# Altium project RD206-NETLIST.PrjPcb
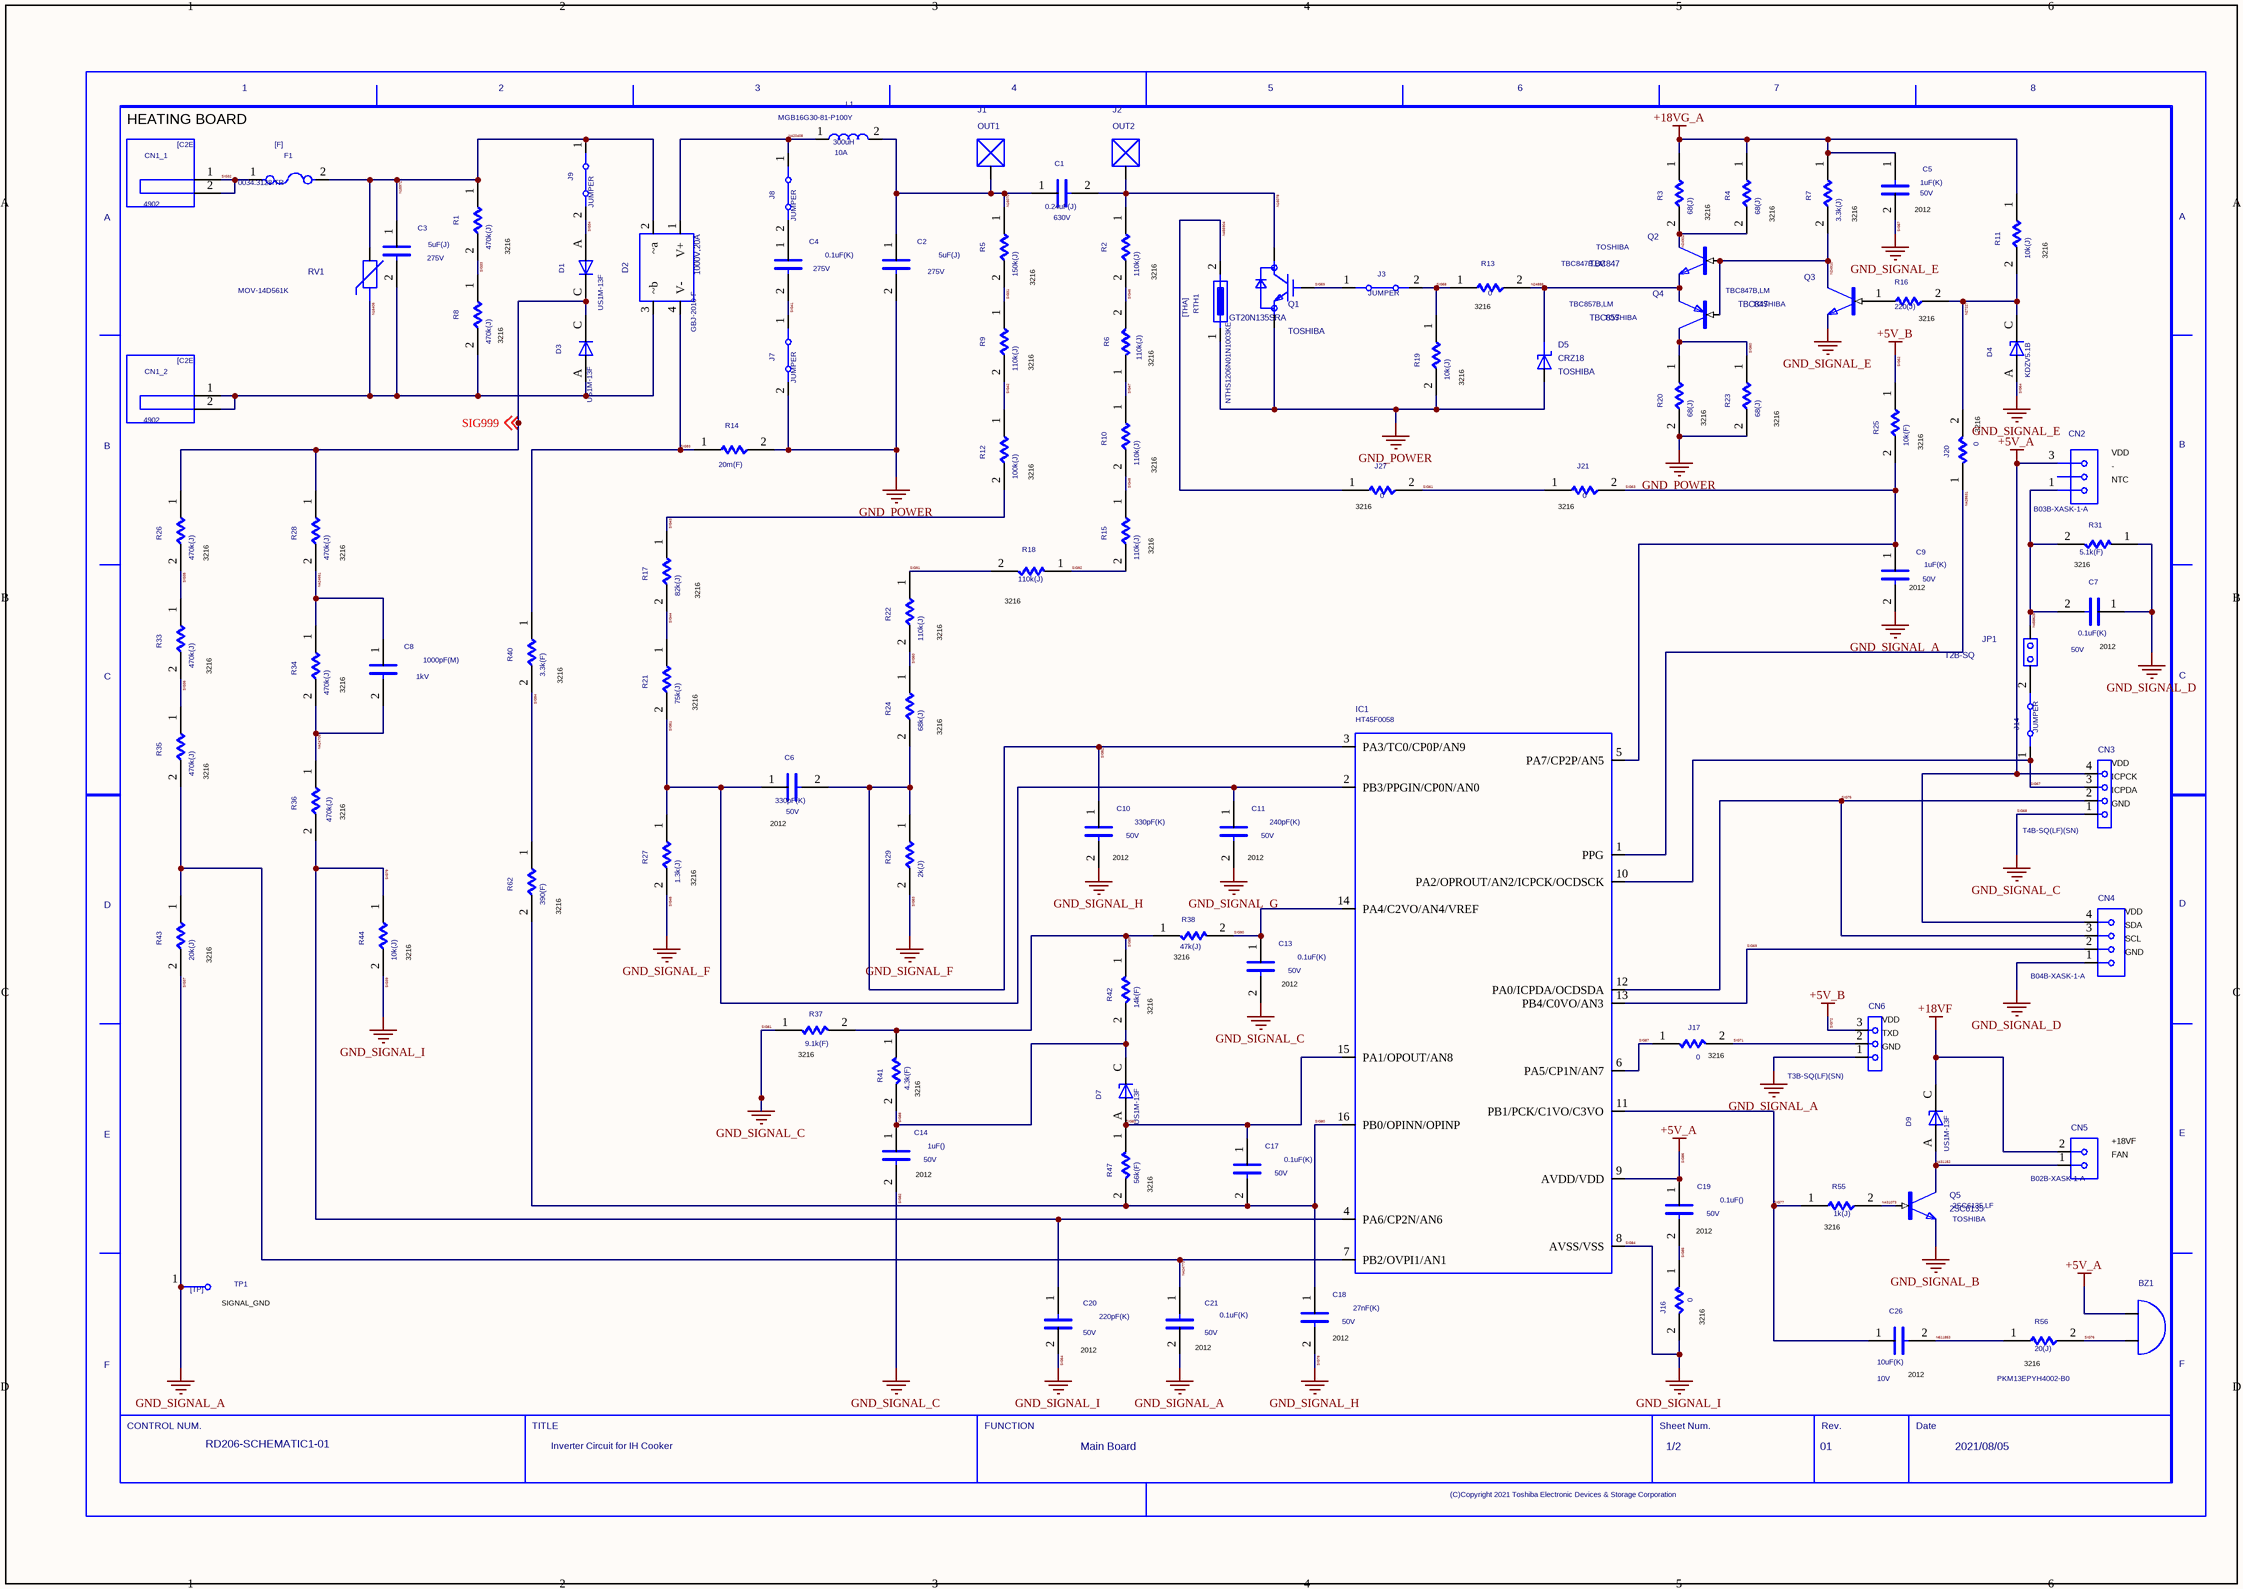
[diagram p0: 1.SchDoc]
2 sheets, 144 parts. Net scope: global (net labels, ports and power ports of the same name join across sheets).
Sheets:
  1.SchDoc
  2.SchDoc

## Sheet 1.SchDoc
size 420 x 297 mm

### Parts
(Parts that share a designator on the sheet are numbered #1, #2 ... from top to bottom, then left to right.)
BZ1  PKM13EPYH4002-B0  [DIP]
C1  VAL2: 630V  VAL1: 0.24uF(J)  (hidden comment: C)
C2  VAL2: 275V  VAL1: 5uF(J)  (hidden comment: C)
C3  VAL2: 275V  VAL1: 5uF(J)  (hidden comment: C)
C4  VAL2: 275V  VAL1: 0.1uF(K)  (hidden comment: C)
C5  VAL2: 50V  VAL1: 1uF(K)  (hidden comment: C)
C6  VAL2: 50V  VAL1: 330pF(K)  (hidden comment: C)
C7  VAL2: 50V  VAL1: 0.1uF(K)  (hidden comment: C)
C8  VAL2: 1kV  VAL1: 1000pF(M)  (hidden comment: C)
C9  VAL2: 50V  VAL1: 1uF(K)  (hidden comment: C)
C10  VAL2: 50V  VAL1: 330pF(K)  (hidden comment: C)
C11  VAL2: 50V  VAL1: 240pF(K)  (hidden comment: C)
C13  VAL2: 50V  VAL1: 0.1uF(K)  (hidden comment: C)
C14  VAL2: 50V  VAL1: 1uF()  (hidden comment: C)
C17  VAL2: 50V  VAL1: 0.1uF(K)  (hidden comment: C)
C18  VAL2: 50V  VAL1: 27nF(K)  (hidden comment: C)
C19  VAL2: 50V  VAL1: 0.1uF()  (hidden comment: C)
C20  VAL2: 50V  VAL1: 220pF(K)  (hidden comment: C)
C21  VAL2: 50V  VAL1: 0.1uF(K)  (hidden comment: C)
C26  VAL2: 10V  VAL1: 10uF(K)  (hidden comment: C)
CN1_1  VAL3: 4902  (hidden comment: C2E)
CN1_2  VAL3: 4902  (hidden comment: C2E)
CN2  VAL3: B03B-XASK-1-A  (hidden comment: CON3S)
CN3  VAL3: T4B-SQ(LF)(SN)  [DIP]  (hidden comment: T4B-SQ)
CN4  B04B-XASK-1-A  [DIP]
CN5  B02B-XASK-1-A  [DIP]
CN6  VAL3: T3B-SQ(LF)(SN)  [DIP]  (hidden comment: T3B-SQ)
D1  VAL3: US1M-13F  (hidden comment: D)
D2  VALUE2: 1000V,20A  VAL3: GBJ-2010-F  [SMA]  (hidden comment: GBJ2010)
D3  VAL3: US1M-13F  (hidden comment: D)
D4  VAL3: KDZV5.1B  (hidden comment: ZD)
D5  CRZ18  MANUFACTURER: TOSHIBA  [S-FLAT]
D7  VAL3: US1M-13F  (hidden comment: ZD)
D9  VAL3: US1M-13F  (hidden comment: ZD)
F1  VAL3: 0034.3128.TR  (hidden comment: F)
IC1  HT45F0058
J1  OUT1
J2  OUT2
J3  VAL3: JUMPER  (hidden comment: JP)
J7  VAL3: JUMPER  (hidden comment: JP)
J8  VAL3: JUMPER  (hidden comment: JP)
J9  VAL3: JUMPER  (hidden comment: JP)
J14  VAL3: JUMPER  (hidden comment: JP)
J16  VAL1: 0  (hidden comment: R)
J17  VAL1: 0  (hidden comment: R)
J20  VAL1: 0  (hidden comment: R)
J21  VAL1: 0  (hidden comment: R)
J27  VAL1: 0  (hidden comment: R)
JP1  T2B-SQ  [DIP]
L1  VAL3: MGB16G30-81-P100Y  VAL2: 10A  VAL1: 300uH  (hidden comment: L)
Q1  GT20N135SRA  MANUFACTURER: TOSHIBA  [TO-247]
Q2  TBC847  USERCOMPTEXT3: TOSHIBA  VAL3: TBC847B,LM  [SOT-23]
Q3  TBC847  USERCOMPTEXT3: TOSHIBA  VAL3: TBC847B,LM  [SOT-23]
Q4  TBC857  USERCOMPTEXT3: TOSHIBA  VAL3: TBC857B,LM  [SOT-23]
Q5  2SC6135  USERCOMPTEXT3: TOSHIBA  VAL3: 2SC6135,LF  [SOT-323]
R1  VAL1: 470k(J)  (hidden comment: R)
R2  VAL1: 110k(J)  (hidden comment: R)
R3  VAL1: 68(J)  (hidden comment: R)
R4  VAL1: 68(J)  (hidden comment: R)
R5  VAL1: 150k(J)  (hidden comment: R)
R6  VAL1: 110k(J)  (hidden comment: R)
R7  VAL1: 3.3k(J)  (hidden comment: R)
R8  VAL1: 470k(J)  (hidden comment: R)
R9  VAL1: 110k(J)  (hidden comment: R)
R10  VAL1: 110k(J)  (hidden comment: R)
R11  VAL1: 10k(J)  (hidden comment: R)
R12  VAL1: 100k(J)  (hidden comment: R)
R13  VAL1: 0  (hidden comment: R)
R14  VAL1: 20m(F)  (hidden comment: R)
R15  VAL1: 110k(J)  (hidden comment: R)
R16  VAL1: 220(J)  (hidden comment: R)
R17  VAL1: 82k(J)  (hidden comment: R)
R18  VAL1: 110k(J)  (hidden comment: R)
R19  VAL1: 10k(J)  (hidden comment: R)
R20  VAL1: 68(J)  (hidden comment: R)
R21  VAL1: 75k(J)  (hidden comment: R)
R22  VAL1: 110k(J)  (hidden comment: R)
R23  VAL1: 68(J)  (hidden comment: R)
R24  VAL1: 68k(J)  (hidden comment: R)
R25  VAL1: 10k(F)  (hidden comment: R)
R26  VAL1: 470k(J)  (hidden comment: R)
R27  VAL1: 1.3k(J)  (hidden comment: R)
R28  VAL1: 470k(J)  (hidden comment: R)
R29  VAL1: 2k(J)  (hidden comment: R)
R31  VAL1: 5.1k(F)  (hidden comment: R)
R33  VAL1: 470k(J)  (hidden comment: R)
R34  VAL1: 470k(J)  (hidden comment: R)
R35  VAL1: 470k(J)  (hidden comment: R)
R36  VAL1: 470k(J)  (hidden comment: R)
R37  VAL1: 9.1k(F)  (hidden comment: R)
R38  VAL1: 47k(J)  (hidden comment: R)
R40  VAL1: 3.3k(F)  (hidden comment: R)
R41  VAL1: 4.3k(F)  (hidden comment: R)
R42  VAL1: 14k(F)  (hidden comment: R)
R43  VAL1: 20k(J)  (hidden comment: R)
R44  VAL1: 10k(J)  (hidden comment: R)
R47  VAL1: 56k(F)  (hidden comment: R)
R55  VAL1: 1k(J)  (hidden comment: R)
R56  VAL1: 20(J)  (hidden comment: R)
R62  VAL1: 390(F)  (hidden comment: R)
RTH1  VAL3: NTHS1206N01N1003KE  (hidden comment: THA)
RV1  VAL3: MOV-14D561K  (hidden comment: VARISTOR)
TP1  TP  (value not drawn)
U?#1  DATE: 2021/08/05  DRAWINGNUMBER: RD206-SCHEMATIC1-01  FUNCTION: Main Board  REVISION: 01  SHEETNUMBER: 1/2  TITLE: Inverter Circuit for IH Cooker  (hidden comment: WAKU_DEF100)

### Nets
+18VF: CN5.2 D9.C
+18VG_A: C5.1 R3.1 R4.1 R7.1 R11.1  [project net SIG26]
GND_POWER: C2.2 D5.A(Anode) J7.2 Q1.3(EMITTER) R14.2 R19.2 R20.2 R23.2 RTH1.1
GND_SIGNAL_A: C9.2 C21.2 CN6.1 R43.2 TP1.1  [also labelled SIG37]  [project net SIG29]
GND_SIGNAL_B: Q5.2(E)  [project net SIG15]
GND_SIGNAL_D: C7.1 CN4.1 R31.1
GND_SIGNAL_G: C11.2
GND_SIGNAL_I: C20.2 IC1.8(AVSS/VSS) J16.2 R44.2  [also labelled SIG39, SIG54, SIG84]  [project net SIG28]
SIG45: R27.2 R29.2  [also labelled GND_SIGNAL_F, SIG53]
SIG57: C5.2 D4.A Q3.2(E)  [also labelled GND_SIGNAL_E, SIG64]
SIG62: CN6.3 R25.1  [also labelled +5V_B, SIG72]
SIG68: C13.2 C14.2 CN3.1 R37.1  [also labelled GND_SIGNAL_C, SIG81, SIG82]
SIG78: C10.2 C18.2  [also labelled GND_SIGNAL_H]
SIG86: BZ1.1 C19.1 CN2.3 CN3.4 CN4.4 IC1.9(AVDD/VDD)  [also labelled +5V_A]
N15972: C3.1 D2.2(~a) F1.2 J9.1 R1.1 RV1.1
N16070: C1.1 C2.1 J1.1 L1.2 R5.1
N16078: C1.2 J2.1 Q1.2(COLLECTOR) R2.1
N16406: C3.2 CN1_2.1 CN1_2.2 D2.3(~b) D3.A R8.2 RV1.2
N24888: D5.C(Cathode) Q2.2(E) Q4.2(E) R13.2
N24902: Q2.3(C) R3.2 R4.2
N24910: Q2.1(B) Q3.3(C) Q4.1(B) R7.2
N27227: D4.C J20.2 R11.2 R16.2
N420408: D2.1(V+) J8.1 L1.1
N424661: C8.1 R28.2 R34.1
N424705: C8.2 R34.2 R36.1
N424773: C21.1 IC1.7(PB2/OVPI1/AN1) R35.2 R43.1
N428631: IC1.1(PPG) J20.1
N431073: Q5.1(B) R55.2
N431152: CN5.1 D9.A Q5.3(C)
N456904: J27.1 RTH1.2
N458626: C7.2 CN2.1 JP1.2 R31.2
N611853: C26.2 R56.1
SIG31: R5.2 R9.1
SIG32: CN1_1.1 CN1_1.2 F1.1
SIG33: R1.2 R8.1
SIG34: D1.A J9.2
SIG35: R26.2 R33.1
SIG36: R33.2 R35.1
SIG41: C4.2 J7.1
SIG42: R9.2 R12.1
SIG43: R12.2 R17.1
SIG44: R17.2 R21.1
SIG46: R2.2 R6.2
SIG47: R6.1 R10.1
SIG48: R10.2 R15.1
SIG50: R22.2 R24.1
SIG51: C6.1 C11.1 IC1.2(PB3/PPGIN/CP0N/AN0) R21.2 R27.1
SIG52: C6.2 C10.1 IC1.3(PA3/TC0/CP0P/AN9) R24.2 R29.1
SIG58: J3.2 R13.1 R19.1
SIG59: J3.1 Q1.1(GATE)
SIG60: Q4.3(C) R20.1 R23.1
SIG61: J21.1 J27.2
SIG63: C9.1 IC1.5(PA7/CP2P/AN5) J21.2 R25.2
SIG67: CN3.3 IC1.10(PA2/OPROUT/AN2/ICPCK/OCDSCK) J14.1
SIG69: CN4.2 IC1.13(PB4/C0VO/AN3)
SIG71: CN6.2 J17.2
SIG75: CN3.2 CN4.3 IC1.12(PA0/ICPDA/OCDSDA)
SIG76: BZ1.2 R56.2
SIG77: C26.1 IC1.11(PB1/PCK/C1VO/C3VO) R55.1
SIG79: C20.1 IC1.4(PA6/CP2N/AN6) R36.2 R44.1
SIG80: C17.2 C18.1 IC1.16(PB0/OPINN/OPINP) R47.2 R62.2
SIG83: C17.1 D7.A IC1.15(PA1/OPOUT/AN8) R47.1
SIG85: C19.2 J16.1
SIG87: IC1.6(PA5/CP1N/AN7) J17.1
SIG88: C14.1 D7.C R41.2 R42.2
SIG89: R37.2 R38.1 R41.1 R42.1
SIG90: C13.1 IC1.14(PA4/C2VO/AN4/VREF) R38.2
SIG91: R18.2 R22.1
SIG92: R15.2 R18.1
SIG93: D2.4(V-) R14.1 R40.1
SIG94: R40.2 R62.1
SIG999: D1.C D3.C R26.1 R28.1 ; off-sheet SIG999
NetC4_1: C4.1 J8.2
NetJ14_2: J14.2 JP1.1
NetQ3_1: Q3.1(B) R16.1

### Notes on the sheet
- HEATING BOARD
- (near R1) 3216
- 3216
- (near R4) 3216
- (near C5) 2012
- (near R11) 3216
- (near R5) 3216
- (near R2) 3216
- (near R13) 3216
- (near R16) 3216
- (near R8) 3216
- (near R9) 3216
- (near R6) 3216
- (near R19) 3216
- (near R20) 3216
- (near R23) 3216
- (near J20) 3216
- VDD
- (near R12) 3216
- (near R10) 3216
- (near J27) 3216
- (near J21) 3216
- -
- NTC
- (near R26) 3216
- (near R28) 3216
- (near R17) 3216
- (near R15) 3216
- (near C9) 2012
- (near R31) 3216
- (near R22) 3216
- (near R18) 3216
- (near C7) 2012
- (near R33) 3216
- (near R40) 3216
- (near R21) 3216
- (near R24) 3216
- (near R35) 3216
- (near CN3) VDD
- (near CN3) ICPCK
- (near CN3) ICPDA
- (near R36) 3216
- (near C6) 2012
- (near C10) 2012
- (near C11) 2012
- (near CN3) GND
- (near R62) 3216
- (near R27) 3216
- (near CN4) VDD
- (near CN4) SDA
- (near R43) 3216
- (near R44) 3216
- (near R38) 3216
- (near C13) 2012
- (near CN4) GND
- (near CN4) SCL
- (near R37) 3216
- (near R42) 3216
- (near J17) 3216
- (near CN6) TXD
- (near CN6) GND
- (near CN6) VDD
- (near R41) 3216
- (near C14) 2012
- (near R47) 3216
- (near CN5) FAN
- (near CN5) +18VF
- (near C19) 2012
- (near R55) 3216
- (near TP1) SIGNAL_GND
- (near C18) 2012
- (near J16) 3216
- (near C20) 2012
- (near C21) 2012
- (near C26) 2012
- (near R56) 3216

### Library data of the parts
BZ1 = BUZZER: PARTNAME: Part13801; MANUFACTURER: Murata; TIME: 16:07:41; UPDATEUSER: t5459927; SAVECOUNT: 1; OriginalSymbolOrigin: (0,0); VALUE2: D12.6xH6.9,4kHz; INSTANCENAME: INS611789
C1 = C: PARTNAME: Part13608; OriginalSymbolOrigin: (2540,7620)
C2 C3 = C: PARTNAME: Part13609; OriginalSymbolOrigin: (2540,7620)
C4 = C: PARTNAME: Part13606; OriginalSymbolOrigin: (2540,7620)
C5 C20 C21 = C#1: PARTNAME: Part6003; OriginalSymbolOrigin: (2540,7620); CaptureCellPackProp: C##1
C6 C7 C9-C11 C13 C14 C17-C19 C26 = C: PARTNAME: Part6003; OriginalSymbolOrigin: (2540,7620)
C8 = C: PARTNAME: Part13607; OriginalSymbolOrigin: (2540,7620)
CN1_1 CN1_2 = C2E: PARTNAME: Part13901; SAVEAREA0: -4733,-209,25099,17942; TIME: 14:34:38; UPDATEUSER: fukuda-y; UPDATETIME: 16:35:06; SAVECOUNT: 10; OriginalSymbolOrigin: (5080,15240)
CN2 = CON3S: PARTNAME: Part13910; TIME: 16:07:41; UPDATEUSER: t5459927; UPDATETIME: 14:26:02; SAVECOUNT: 3; SAVEAREA0: -3803,-10405,11105,524; OriginalSymbolOrigin: (0,0)
CN3 = HEADER_4P: PARTNAME: Part13906; MANUFACTURER: JST; TIME: 16:07:41; UPDATEUSER: t5459927; SAVECOUNT: 1; SAVEAREA0: -6996,-12954,11642,710; OriginalSymbolOrigin: (0,0); VALUE2: for Debugger,(NM); INSTANCENAME: INS493247
CN4 = CON4S: PARTNAME: Part13904; MANUFACTURER: JST; TIME: 16:07:41; UPDATEUSER: t5459927; SAVECOUNT: 1; SAVEAREA0: -5711,-12954,12927,710; OriginalSymbolOrigin: (0,0); VALUE2: to DISPLAY BOARD; INSTANCENAME: INS493000
CN5 = CON2S: PARTNAME: Part13902; MANUFACTURER: JST; TIME: 16:07:41; UPDATEUSER: t5459927; SAVECOUNT: 1; SAVEAREA0: -1901,-7788,9280,409; OriginalSymbolOrigin: (0,0); VALUE2: to FAN; INSTANCENAME: INS493353
CN6 = HEADER_3P: PARTNAME: Part13908; MANUFACTURER: JST; TIME: 16:07:41; UPDATEUSER: t5459927; SAVECOUNT: 1; SAVEAREA0: -5093,-10384,9816,546; OriginalSymbolOrigin: (0,0); VALUE2: for UART Debug; INSTANCENAME: INS667453
D1 D3 = D: PARTNAME: Part13451; SAVEAREA0: -225,-91,12804,7836; SAVECOUNT: 3; TIME: 14:49:55; UPDATEUSER: 19870035; UPDATETIME: 14:20:16; OriginalSymbolOrigin: (5080,5080)
D2 = D25XB: PARTNAME: Part13452; MANUFACTURER: DIODES; TIME: 16:07:41; UPDATEUSER: t5459927; SAVECOUNT: 1; SAVEAREA0: -3247,-11751,15521,2008; OriginalSymbolOrigin: (0,0); INSTANCENAME: INS420197
D4 = ZD: PARTNAME: Part4291; SAVEAREA0: -4630,-153,17114,13055; TIME: 14:49:55; UPDATEUSER: fukuda-y; UPDATETIME: 08:18:42; SAVECOUNT: 6; OriginalSymbolOrigin: (5080,5080)
D5 = DIODE_ZENER: PARTNAME: Part4291; TIME: 16:07:41; UPDATEUSER: t5459927; SAVECOUNT: 1; OriginalSymbolOrigin: (0,0); INSTANCENAME: INS25179
D7 D9 = ZD: PARTNAME: Part13451; SAVEAREA0: -4630,-153,17114,13055; TIME: 14:49:55; UPDATEUSER: fukuda-y; UPDATETIME: 08:18:42; SAVECOUNT: 6; OriginalSymbolOrigin: (5080,5080)
F1 = F: PARTNAME: Part13701; OriginalSymbolOrigin: (2540,5080); VAL2: 12.5A 250VAC
IC1 = HT45F0058: PARTNAME: Part2183; MANUFACTURER: HOLTEK; TIME: 16:07:41; UPDATEUSER: t5459927; UPDATETIME: 09:12:11; SAVECOUNT: 2; SAVEAREA0: -96097,-76323,141060,32998; OriginalSymbolOrigin: (0,0)
J1 = TERMINAL: PARTNAME: Part13909; PART_NUMBER: for Heating coil; TIME: 16:07:41; UPDATEUSER: t5459927; SAVECOUNT: 1; SAVEAREA0: -3180,-7788,8001,409; OriginalSymbolOrigin: (0,0); INSTANCENAME: INS418589
J2 = TERMINAL: PARTNAME: Part13909; PART_NUMBER: for Heating coil; TIME: 16:07:41; UPDATEUSER: t5459927; SAVECOUNT: 1; SAVEAREA0: -3180,-7788,8001,409; OriginalSymbolOrigin: (0,0); VAL3: OUT1; INSTANCENAME: INS418681
J3 J7 J8 = JP: PARTNAME: Part13917; OriginalSymbolOrigin: (2540,5080)
J9 J14 = JP: PARTNAME: Part13915; OriginalSymbolOrigin: (2540,5080)
J16 J17 J20 J21 J27 R1-R13 R15-R29 R31 R33-R37 R40-R44 R47 R55 R56 R62 = R: PARTNAME: Part4004; OriginalSymbolOrigin: (5080,5080)
JP1 = HEADER: PARTNAME: Part13905; MANUFACTURER: JST; TIME: 16:07:41; UPDATEUSER: t5459927; SAVECOUNT: 1; SAVEAREA0: -2956,-6337,7768,1525; OriginalSymbolOrigin: (0,0); VAL3: T2B-SQ(LF)(SN); INSTANCENAME: INS520211
L1 = L: PARTNAME: Part13301; OriginalSymbolOrigin: (2540,5080)
Q1 = IGBT: PARTNAME: Part13501; TIME: 16:07:41; UPDATEUSER: t5459927; SAVECOUNT: 1; OriginalSymbolOrigin: (0,0); INSTANCENAME: INS24255
Q2 = 2SC: PARTNAME: Part5004; TIME: 16:07:41; UPDATEUSER: t5459927; SAVECOUNT: 1; OriginalSymbolOrigin: (0,2540); INSTANCENAME: INS24481
Q3 = 2SC: PARTNAME: Part5004; TIME: 16:07:41; UPDATEUSER: t5459927; SAVECOUNT: 1; OriginalSymbolOrigin: (0,2540); INSTANCENAME: INS24374
Q4 = 2SA: PARTNAME: Part5004; TIME: 16:07:41; UPDATEUSER: t5459927; SAVECOUNT: 1; OriginalSymbolOrigin: (0,2540); INSTANCENAME: INS24550
Q5 = 2SC: PARTNAME: Part13502; TIME: 16:07:41; UPDATEUSER: t5459927; SAVECOUNT: 1; OriginalSymbolOrigin: (0,2540); INSTANCENAME: INS429563
R14 = R: PARTNAME: Part13402; OriginalSymbolOrigin: (5080,5080)
R38 = R#1: PARTNAME: Part4004; OriginalSymbolOrigin: (5080,5080); CaptureCellPackProp: R##1
RTH1 = THA: PARTNAME: Part3109; SAVECOUNT: 3; SAVEAREA0: -562,-143,15615,10489; TIME: 16:37:29; UPDATEUSER: sato-yr; OriginalSymbolOrigin: (2540,5080)
RV1 = VARISTOR: PARTNAME: Part13302; TIME: 16:07:41; UPDATEUSER: t5459927; UPDATETIME: 09:40:33; SAVECOUNT: 2; SAVEAREA0: -22723,-23461,27592,13427; OriginalSymbolOrigin: (0,-2540)
TP1 = TP: PARTNAME: Part13998; TIME: 16:12:21; UPDATEUSER: fukuda-y; UPDATETIME: 16:18:11; SAVECOUNT: 2; SAVEAREA0: -242,-92,12810,7836; OriginalSymbolOrigin: (0,7620)
U?#1 = WAKU_DEF100: PLOTTIME: HH:MM; SAVEAREA0: 148187,-66180,486823,89919; TIME: 14:30:25; UPDATEUSER: t5459927; UPDATETIME: 11:15:29; SAVECOUNT: 6; OriginalSymbolOrigin: (10160,284480)

## Sheet 2.SchDoc
size 420 x 297 mm
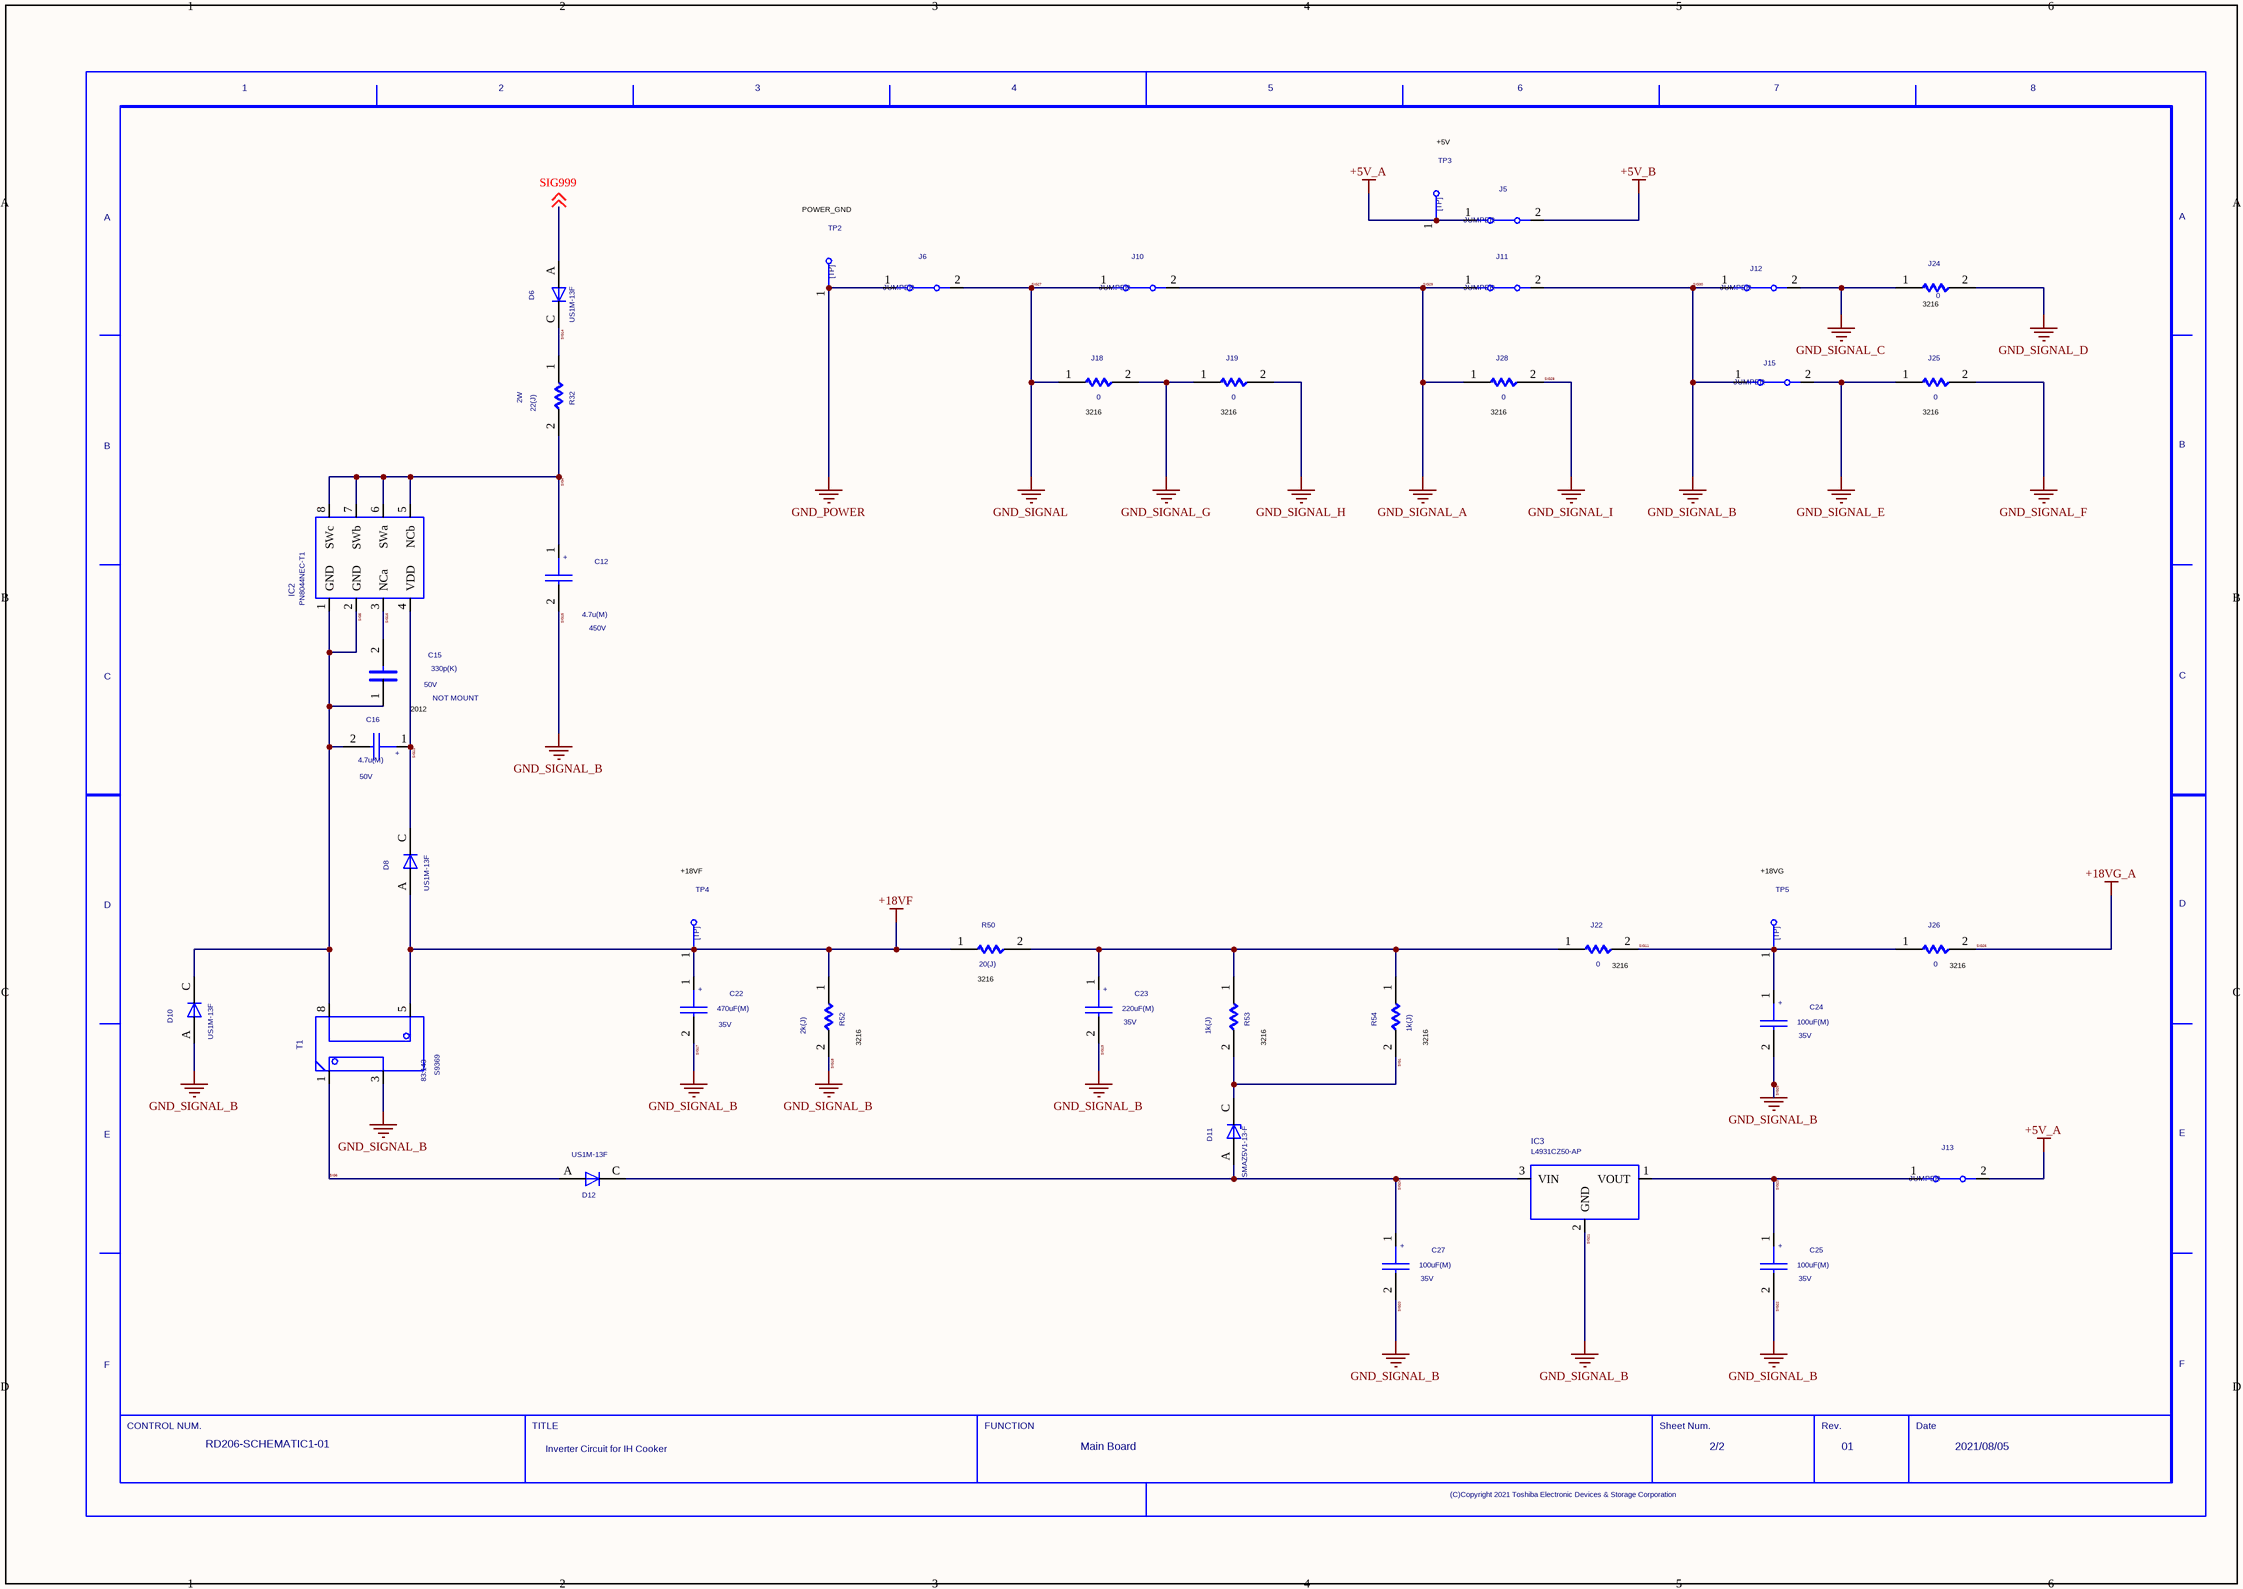
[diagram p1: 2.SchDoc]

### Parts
(Parts that share a designator on the sheet are numbered #1, #2 ... from top to bottom, then left to right.)
C12  VAL2: 450V  VAL1: 4.7u(M)  (hidden comment: CP)
C15  NOTMOUNT: NOT MOUNT  VAL2: 50V  VAL1: 330p(K)  (hidden comment: C)
C16  VAL2: 50V  VAL1: 4.7u(M)  (hidden comment: CP)
C22  VAL2: 35V  VAL1: 470uF(M)  (hidden comment: CP)
C23  VAL2: 35V  VAL1: 220uF(M)  (hidden comment: CP)
C24  VAL2: 35V  VAL1: 100uF(M)  (hidden comment: CP)
C25  VAL2: 35V  VAL1: 100uF(M)  (hidden comment: CP)
C27  VAL2: 35V  VAL1: 100uF(M)  (hidden comment: CP)
D6  VAL3: US1M-13F  (hidden comment: D)
D8  VAL3: US1M-13F  (hidden comment: D)
D10  VAL3: US1M-13F  (hidden comment: D)
D11  VAL3: SMAZ5V1-13-F  (hidden comment: ZD)
D12  VAL3: US1M-13F  (hidden comment: D)
IC2  VAL3: PN8044NEC-T1  (hidden comment: PN8044NEC_T1)
IC3  VAL3: L4931CZ50-AP  (hidden comment: 7805)
J5  VAL3: JUMPER  (hidden comment: JP)
J6  VAL3: JUMPER  (hidden comment: JP)
J10  VAL3: JUMPER  (hidden comment: JP)
J11  VAL3: JUMPER  (hidden comment: JP)
J12  VAL3: JUMPER  (hidden comment: JP)
J13  VAL3: JUMPER  (hidden comment: JP)
J15  VAL3: JUMPER  (hidden comment: JP)
J18  VAL1: 0  (hidden comment: R)
J19  VAL1: 0  (hidden comment: R)
J22  VAL1: 0  (hidden comment: R)
J24  VAL1: 0  (hidden comment: R)
J25  VAL1: 0  (hidden comment: R)
J26  VAL1: 0  (hidden comment: R)
J28  VAL1: 0  (hidden comment: R)
R32  VAL2: 2W  VAL1: 22(J)  (hidden comment: R)
R50  VAL1: 20(J)  (hidden comment: R)
R52  VAL1: 2k(J)  (hidden comment: R)
R53  VAL1: 1k(J)  (hidden comment: R)
R54  VAL1: 1k(J)  (hidden comment: R)
T1  VAL3: S9369  VAL1: 83:143  (hidden comment: EE10)
TP2  TP  (value not drawn)
TP3  TP  (value not drawn)
TP4  TP  (value not drawn)
TP5  TP  (value not drawn)
U?#2  DATE: 2021/08/05  FUNCTION: Main Board  TITLE: Inverter Circuit for IH Cooker  DRAWINGNUMBER: RD206-SCHEMATIC1-01  REVISION: 01  SHEETNUMBER: 2/2  (hidden comment: WAKU_DEF100)

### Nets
+5V_A: J5.1 J13.2 TP3.1  [project net SIG86]
+5V_B: J5.2  [project net SIG62]
+18VF: C22.1 D8.A R50.1 R52.1 T1.5 TP4.1
GND_POWER: J6.1 TP2.1
GND_SIGNAL_C: J12.2 J24.1  [project net SIG68]
GND_SIGNAL_D: J24.2
GND_SIGNAL_E: J15.2 J25.1  [project net SIG57]
GND_SIGNAL_F: J25.2  [project net SIG45]
GND_SIGNAL_G: J18.2 J19.1
GND_SIGNAL_H: J19.2  [project net SIG78]
SIG15: C12.2 C22.2 C23.2 C24.2 C25.2 C27.2 D10.A IC3.2(GND) J11.2 J12.1 J15.1 R52.2 T1.3  [also labelled GND_SIGNAL_B, SIG17, SIG18, SIG19, SIG20, SIG21, SIG22, SIG25, SIG30]
SIG26: J26.2  [also labelled +18VG_A]
SIG27: J6.2 J10.1 J18.1  [also labelled GND_SIGNAL]
SIG28: J28.2  [also labelled GND_SIGNAL_I]
SIG29: J10.2 J11.1 J28.1  [also labelled GND_SIGNAL_A]
SIG1: D11.C R53.2 R54.2
SIG4: C12.1 IC2.5(NCb) IC2.6(SWa) IC2.7(SWb) IC2.8(SWc) R32.2
SIG5: C15.1 C16.2 D10.C IC2.1(GND) IC2.2(GND) T1.8
SIG6: D12.A T1.1
SIG10: C23.1 J22.1 R50.2 R53.1 R54.1
SIG11: C24.1 J22.2 J26.1 TP5.1
SIG13: C16.1 D8.C IC2.4(VDD)
SIG14: D6.C R32.1
SIG16: C15.2 IC2.3(NCa)
SIG23: C25.1 IC3.1(VOUT) J13.1
SIG24: C27.1 D11.A D12.C IC3.3(VIN)
SIG999: D6.A ; off-sheet SIG999

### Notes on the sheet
- +5V
- POWER_GND
- (near J24) 3216
- (near J18) 3216
- (near J19) 3216
- (near J28) 3216
- (near J25) 3216
- 2012
- +18VF
- +18VG
- (near R50) 3216
- (near J22) 3216
- (near J26) 3216
- (near R52) 3216
- (near R53) 3216
- (near R54) 3216

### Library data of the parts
C12 C22 = CP: PARTNAME: Part13601; SAVEAREA0: -1450,-153,20294,13055; SAVECOUNT: 52; TIME: 15:02:55; UPDATEUSER: fukuda-y; UPDATETIME: 16:13:42; OriginalSymbolOrigin: (2540,10160)
C15 = C: as C6 on sheet 1
C16 = CP: PARTNAME: Part13603; SAVEAREA0: -1450,-153,20294,13055; SAVECOUNT: 52; TIME: 15:02:55; UPDATEUSER: fukuda-y; UPDATETIME: 16:13:42; OriginalSymbolOrigin: (2540,10160)
C23 = CP: PARTNAME: Part13604; SAVEAREA0: -1450,-153,20294,13055; SAVECOUNT: 52; TIME: 15:02:55; UPDATEUSER: fukuda-y; UPDATETIME: 16:13:42; OriginalSymbolOrigin: (2540,10160)
C24 C25 C27 = CP: PARTNAME: Part13605; SAVEAREA0: -1450,-153,20294,13055; SAVECOUNT: 52; TIME: 15:02:55; UPDATEUSER: fukuda-y; UPDATETIME: 16:13:42; OriginalSymbolOrigin: (2540,10160)
D6 D8 D10 D12 = D: as D1 on sheet 1
D11 = ZD: as D7 on sheet 1
IC2 = PN8044NEC_T1: PARTNAME: Part13001; TIME: 16:07:41; UPDATEUSER: t5459927; UPDATETIME: 09:18:27; SAVECOUNT: 2; SAVEAREA0: -16422,-15263,31006,6599; OriginalSymbolOrigin: (0,0); COMPONENTNAME: PN8044NEC-T1_PN8044NEC-T1.Normal_package
IC3 = 7805: PARTNAME: Part13002; TIME: 16:07:41; UPDATEUSER: t5459927; UPDATETIME: 09:17:01; SAVECOUNT: 2; SAVEAREA0: -5463,-13073,25154,1040; OriginalSymbolOrigin: (0,0)
J5 J10 J11 = JP: as J9 on sheet 1
J6 = JP: as J3 on sheet 1
J12 J13 = JP: PARTNAME: Part13913; OriginalSymbolOrigin: (2540,5080)
J15 = JP: PARTNAME: Part13911; OriginalSymbolOrigin: (2540,5080)
J18 J19 J22 J24-J26 J28 R50 R52-R54 = R: as J16 on sheet 1
R32 = R: PARTNAME: Part13401; OriginalSymbolOrigin: (5080,5080)
T1 = EE10: PARTNAME: Part13303; TIME: 16:07:41; UPDATEUSER: t5459927; UPDATETIME: 09:16:10; SAVECOUNT: 2; SAVEAREA0: -29920,-23417,50107,13472; OriginalSymbolOrigin: (0,0)
TP2-TP5 = TP: as TP1 on sheet 1
U?#2 = WAKU_DEF100: as U?#1 on sheet 1

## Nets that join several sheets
+18VF: 1 (CN5.2 D9.C), 2 (6 pins)
GND_POWER: 1 (9 pins), 2 (J6.1 TP2.1)
GND_SIGNAL_D: 1 (C7.1 CN4.1 R31.1), 2 (J24.2)
GND_SIGNAL_G: 1 (C11.2), 2 (J18.2 J19.1)
SIG15: 1 (Q5.2), 2 (13 pins)
SIG26: 1 (5 pins), 2 (J26.2)
SIG28: 1 (C20.2 IC1.8 J16.2 R44.2), 2 (J28.2)
SIG29: 1 (5 pins), 2 (J10.2 J11.1 J28.1)
SIG45: 1 (R27.2 R29.2), 2 (J25.2)
SIG57: 1 (C5.2 D4.A Q3.2), 2 (J15.2 J25.1)
SIG62: 1 (CN6.3 R25.1), 2 (J5.2)
SIG68: 1 (C13.2 C14.2 CN3.1 R37.1), 2 (J12.2 J24.1)
SIG78: 1 (C10.2 C18.2), 2 (J19.2)
SIG86: 1 (6 pins), 2 (J5.1 J13.2 TP3.1)
SIG999: 1 (D1.C D3.C R26.1 R28.1), 2 (D6.A)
